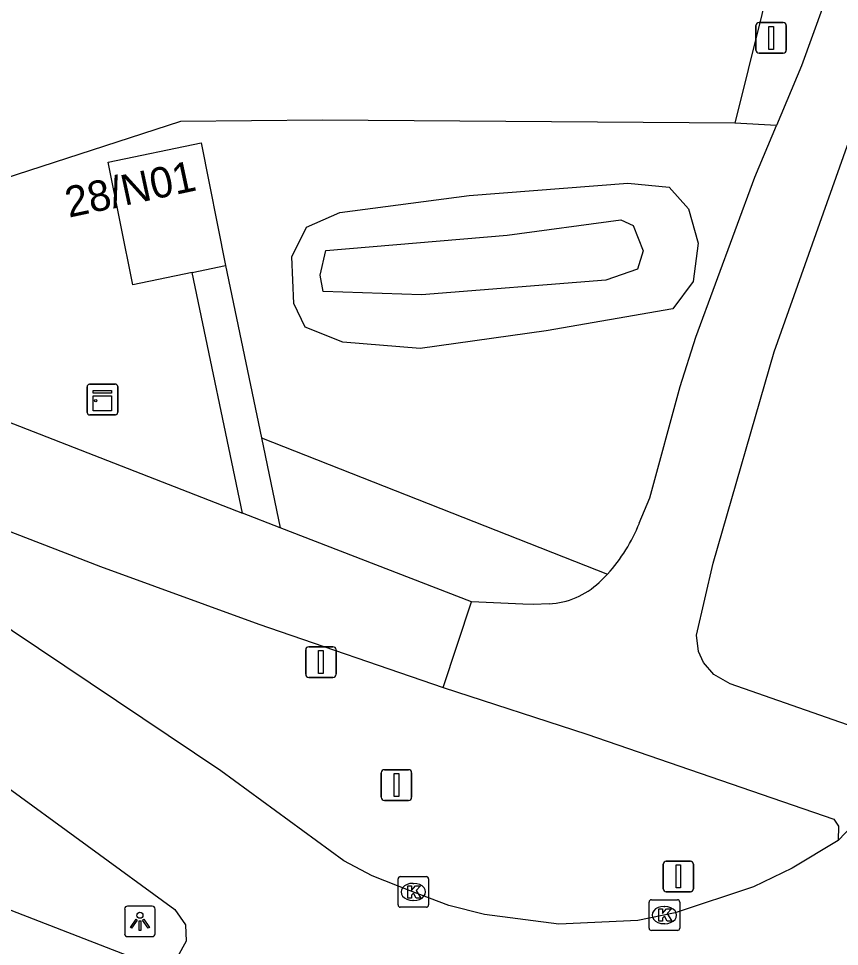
# Model space of a CAD drawing. Extents: x 156141 to 158132, y 385651 to 388399.
# Drawn here: x 156304.31 to 156331.14, y 386510.09 to 386540.41 of the extents above; entities that cross this region are included whole.
import ezdxf

# ---------------------------------------------------------------- set-up
doc = ezdxf.new("R2010")
doc.units = 0
for name, color, linetype in [('IMGEO_Berm_groen', 7, 'Continuous'), ('IMGEO_Bouwland', 7, 'Continuous'), ('IMGEO_Fietspad_gesloten', 7, 'Continuous'), ('IMGEO_Groenvoorziening', 7, 'Continuous'), ('IMGEO_Kast', 7, 'Continuous'), ('IMGEO_Kolk', 7, 'Continuous'), ('IMGEO_Lichtpunt', 7, 'Continuous'), ('IMGEO_Pand', 7, 'Continuous'), ('IMGEO_Pand_nummerreeks', 7, 'Continuous'), ('IMGEO_Rijbaan_lokaal_gesloten', 7, 'Continuous'), ('IMGEO_Verkeersbordpaal', 7, 'Continuous'), ('IMGEO_Voetpad_open', 7, 'Continuous')]:
    doc.layers.add(name, color=color, linetype=linetype)

msp = doc.modelspace()

# ---------------------------------------------------------------- linework, layer by layer
at = {"layer": 'IMGEO_Berm_groen'}
for points in [[(156358.914, 386681.214), (156356.118, 386665.332), (156348.768, 386626.891), (156344.27, 386606.243), (156337.845, 386577.757), (156327.718, 386536.986)], [(156329.08, 386536.913), (156327.718, 386536.986)], [(156312.247, 386526.707), (156323.558, 386522.259)]]:
    msp.add_lwpolyline(points, dxfattribs=at)
at = {"layer": 'IMGEO_Bouwland'}
msp.add_lwpolyline([(156327.718, 386536.986), (156314.236, 386537.081), (156309.604, 386537.043), (156302.98, 386534.895), (156300.78, 386542.538), (156301.952, 386551.718)], dxfattribs=at)
at = {"layer": 'IMGEO_Fietspad_gesloten'}
for points in [[(156348.163, 386611.714), (156343.943, 386590.004), (156341.252, 386578.081), (156338.908, 386569.228), (156337.052, 386561.839), (156334.06, 386550.854), (156331.742, 386543.951), (156329.901, 386538.856), (156329.08, 386536.913)], [(156334.214, 386516.809), (156333.87, 386516.678), (156333.544, 386516.668), (156331.617, 386517.261), (156327.569, 386518.673), (156327.033, 386518.98), (156326.698, 386519.369), (156326.529, 386519.727), (156326.464, 386520.258), (156327.01, 386522.618), (156329, 386529.519), (156331.388, 386536.237), (156333.27, 386540.153), (156340.71, 386545.321), (156341.097, 386545.374), (156341.486, 386545.29), (156341.773, 386545.133), (156341.96, 386544.868), (156341.997, 386543.534)], [(156324.596, 386523.924), (156324.936, 386524.744), (156325.935, 386528.385), (156326.447, 386529.996), (156328.367, 386535.225), (156329.08, 386536.913)], [(156299.915, 386528.814), (156311.622, 386524.249)], [(156292.75, 386528.181), (156300.726, 386524.92), (156306.982, 386522.509), (156312.164, 386520.621), (156318.18, 386518.557)], [(156312.861, 386523.766), (156311.622, 386524.249)], [(156319.111, 386521.349), (156312.861, 386523.766)], [(156323.558, 386522.259), (156323.283, 386521.987)], [(156318.18, 386518.557), (156319.111, 386521.349)], [(156321.646, 386521.284), (156321.133, 386521.268), (156320.786, 386521.275), (156319.111, 386521.349)], [(156318.18, 386518.557), (156322.883, 386517.032), (156330.955, 386514.254), (156331.103, 386514.021), (156331.099, 386513.557)]]:
    msp.add_lwpolyline(points, dxfattribs=at)
for centre, radius, start, end in [((156319.467, 386525.966), 5.521, 317.8239, 338.2954), ((156321.502, 386523.877), 2.597, 273.1821, 313.2995)]:
    msp.add_arc(centre, radius, start, end, dxfattribs=at)
at = {"layer": 'IMGEO_Groenvoorziening'}
for points in [[(156324.217, 386535.031), (156325.576, 386534.896), (156326.203, 386534.188), (156326.521, 386533.069), (156326.359, 386531.817), (156325.692, 386530.921), (156321.551, 386530.208), (156317.436, 386529.624), (156314.905, 386529.836), (156313.679, 386530.328), (156313.301, 386531.095), (156313.239, 386532.618), (156313.717, 386533.589), (156314.803, 386534.068), (156319.03, 386534.625), (156324.217, 386535.031)], [(156317.48, 386531.375), (156314.267, 386531.49), (156314.165, 386532.027), (156314.349, 386532.826), (156320.273, 386533.334), (156323.996, 386533.828), (156324.395, 386533.645), (156324.723, 386532.819), (156324.54, 386532.22), (156323.498, 386531.855), (156317.48, 386531.375)]]:
    msp.add_lwpolyline(points, dxfattribs=at)
at = {"layer": 'IMGEO_Kast'}
for p, q in [((156306.625, 386528.461), (156307.466, 386528.461)), ((156307.466, 386528.461), (156306.625, 386528.461)), ((156306.55, 386527.536), (156306.55, 386528.377)), ((156306.55, 386528.377), (156306.55, 386527.536)), ((156307.55, 386528.386), (156307.55, 386527.545)), ((156307.55, 386527.545), (156307.55, 386528.386)), ((156307.475, 386527.461), (156306.634, 386527.461)), ((156306.634, 386527.461), (156307.475, 386527.461))]:
    msp.add_line(p, q, dxfattribs=at)
for points in [[(156306.745, 386528.251), (156307.345, 386528.251), (156307.345, 386528.166), (156306.745, 386528.166), (156306.745, 386528.251)], [(156306.745, 386528.076), (156307.345, 386528.076), (156307.345, 386527.587), (156306.745, 386527.587), (156306.745, 386528.076)]]:
    msp.add_lwpolyline(points, dxfattribs=at)
msp.add_circle((156306.829, 386527.925), 0.0377, dxfattribs=at)
for centre, start, end in [((156306.628, 386528.383), 92.4484, 184.2845), ((156306.628, 386528.383), 92.4484, 184.2845), ((156307.472, 386528.383), 2.4484, 94.2845), ((156307.472, 386528.383), 2.4484, 94.2845), ((156307.472, 386527.539), 272.4484, 4.2845), ((156307.472, 386527.539), 272.4484, 4.2845), ((156306.628, 386527.539), 182.4484, 274.2845), ((156306.628, 386527.539), 182.4484, 274.2845)]:
    msp.add_arc(centre, 0.0779, start, end, dxfattribs=at)
at = {"layer": 'IMGEO_Kolk'}
for p, q in [((156316.709, 386511.449), (156316.709, 386512.301)), ((156316.784, 386512.375), (156317.636, 386512.375)), ((156317.197, 386512.155), (156317.222, 386512.155)), ((156317.71, 386512.301), (156317.71, 386511.449)), ((156317.22, 386511.595), (156317.195, 386511.595)), ((156324.914, 386510.692), (156324.914, 386511.544)), ((156324.989, 386511.618), (156325.841, 386511.618)), ((156325.915, 386511.544), (156325.915, 386510.692)), ((156317.636, 386511.375), (156316.784, 386511.375)), ((156325.402, 386511.398), (156325.427, 386511.398)), ((156325.841, 386510.618), (156324.989, 386510.618)), ((156325.425, 386510.838), (156325.4, 386510.838))]:
    msp.add_line(p, q, dxfattribs=at)
for points in [[(156316.709, 386511.449), (156316.709, 386512.301)], [(156316.784, 386512.375), (156317.636, 386512.375)], [(156317.71, 386512.301), (156317.71, 386511.449)], [(156317.03, 386512.075), (156317.153, 386512.075), (156317.153, 386511.924), (156317.283, 386512.075), (156317.447, 386512.075), (156317.301, 386511.924), (156317.454, 386511.675), (156317.302, 386511.675), (156317.217, 386511.839), (156317.153, 386511.772), (156317.153, 386511.675), (156317.03, 386511.675), (156317.03, 386512.075)], [(156324.914, 386510.692), (156324.914, 386511.544)], [(156324.989, 386511.618), (156325.841, 386511.618)], [(156325.915, 386511.544), (156325.915, 386510.692)], [(156317.636, 386511.375), (156316.784, 386511.375)], [(156325.235, 386511.318), (156325.358, 386511.318), (156325.358, 386511.167), (156325.488, 386511.318), (156325.652, 386511.318), (156325.506, 386511.167), (156325.659, 386510.918), (156325.507, 386510.918), (156325.422, 386511.082), (156325.358, 386511.015), (156325.358, 386510.918), (156325.235, 386510.918), (156325.235, 386511.318)], [(156325.841, 386510.618), (156324.989, 386510.618)]]:
    msp.add_lwpolyline(points, dxfattribs=at)
for centre, start, end in [((156316.786, 386512.299), 91.552, 178.448), ((156316.786, 386512.299), 91.552, 178.448), ((156317.634, 386512.299), 1.552, 88.448), ((156317.634, 386512.299), 1.552, 88.448), ((156324.991, 386511.542), 91.552, 178.448), ((156324.991, 386511.542), 91.552, 178.448), ((156325.839, 386511.542), 1.552, 88.448), ((156325.839, 386511.542), 1.552, 88.448), ((156316.786, 386511.451), 181.552, 268.448), ((156316.786, 386511.451), 181.552, 268.448), ((156317.634, 386511.451), 271.552, 358.448), ((156317.634, 386511.451), 271.552, 358.448), ((156324.991, 386510.694), 181.552, 268.448), ((156324.991, 386510.694), 181.552, 268.448), ((156325.839, 386510.694), 271.552, 358.448), ((156325.839, 386510.694), 271.552, 358.448)]:
    msp.add_arc(centre, 0.0765, start, end, dxfattribs=at)
for centre, major_axis, ratio, start_param, end_param in [((156317.196, 386511.875), (-0.387, 0.002), 0.722429, 4.712389, 7.853982), ((156317.221, 386511.875), (-0.39, 0.002), 0.717154, 1.570796, 4.712389), ((156325.401, 386511.118), (-0.387, 0.002), 0.722429, 4.712389, 7.853982), ((156325.426, 386511.118), (-0.39, 0.002), 0.717154, 1.570796, 4.712389)]:
    msp.add_ellipse(centre, major_axis=major_axis, ratio=ratio, start_param=start_param, end_param=end_param, dxfattribs=at)
at = {"layer": 'IMGEO_Lichtpunt'}
for p, q in [((156307.776, 386511.317), (156307.776, 386510.51)), ((156307.776, 386511.317), (156307.776, 386510.51)), ((156308.678, 386511.412), (156307.87, 386511.412)), ((156308.678, 386511.412), (156307.87, 386511.412)), ((156308.772, 386510.51), (156308.772, 386511.317)), ((156308.772, 386510.51), (156308.772, 386511.317)), ((156307.87, 386510.416), (156308.678, 386510.416)), ((156307.87, 386510.416), (156308.678, 386510.416))]:
    msp.add_line(p, q, dxfattribs=at)
for points in [[(156308.15, 386510.981), (156308.189, 386510.953), (156308.001, 386510.691), (156307.963, 386510.718), (156308.15, 386510.981)], [(156308.252, 386510.933), (156308.299, 386510.933), (156308.299, 386510.611), (156308.252, 386510.611), (156308.252, 386510.933)], [(156308.362, 386510.953), (156308.4, 386510.98), (156308.587, 386510.718), (156308.548, 386510.69), (156308.362, 386510.953)]]:
    msp.add_lwpolyline(points, dxfattribs=at)
msp.add_circle((156308.275, 386511.115), 0.0994, dxfattribs=at)
for centre, start, end in [((156307.87, 386511.317), 90, 180), ((156307.87, 386511.317), 90, 180), ((156308.678, 386511.317), 0, 90), ((156308.678, 386511.317), 0, 90), ((156307.87, 386510.51), 180, 270), ((156307.87, 386510.51), 180, 270), ((156308.678, 386510.51), 270, 0), ((156308.678, 386510.51), 270, 360)]:
    msp.add_arc(centre, 0.0946, start, end, dxfattribs=at)
at = {"layer": 'IMGEO_Pand'}
for points in [[(156309.985, 386532.114), (156308.042, 386531.705), (156307.234, 386535.712), (156310.277, 386536.35), (156311.07, 386532.343)], [(156309.985, 386532.114), (156311.07, 386532.343)]]:
    msp.add_lwpolyline(points, dxfattribs=at)
at = {"layer": 'IMGEO_Rijbaan_lokaal_gesloten'}
for points in [[(156279.45, 386524.804), (156292.191, 386519.892), (156293.29, 386519.47), (156293.425, 386519.418), (156303.669, 386515.482), (156309.414, 386511.3), (156309.768, 386510.799), (156309.786, 386510.272), (156309.503, 386509.752), (156309.018, 386509.516), (156308.448, 386509.57), (156294.031, 386515.158), (156293.895, 386515.211), (156292.782, 386515.644), (156280.043, 386520.581)], [(156331.099, 386513.557), (156329.596, 386512.65), (156328.331, 386512.037), (156325.767, 386511.191), (156324.552, 386510.938), (156321.96, 386510.826), (156319.539, 386511.139), (156318.366, 386511.435), (156317.104, 386511.915), (156315.868, 386512.406), (156314.943, 386512.888), (156310.923, 386515.834), (156304.102, 386520.406), (156302.029, 386522.003)], [(156334.214, 386516.809), (156331.099, 386513.557)]]:
    msp.add_lwpolyline(points, dxfattribs=at)
at = {"layer": 'IMGEO_Verkeersbordpaal'}
for p, q in [((156328.408, 386539.374), (156328.408, 386540.174)), ((156328.408, 386540.174), (156328.408, 386539.374)), ((156328.508, 386540.274), (156329.298, 386540.274)), ((156329.298, 386540.274), (156328.508, 386540.274)), ((156329.398, 386540.174), (156329.398, 386539.374)), ((156329.398, 386539.374), (156329.398, 386540.174)), ((156329.298, 386539.274), (156328.508, 386539.274)), ((156328.508, 386539.274), (156329.298, 386539.274)), ((156313.694, 386518.984), (156313.694, 386519.784)), ((156313.694, 386519.784), (156313.694, 386518.984)), ((156313.794, 386519.884), (156314.584, 386519.884)), ((156314.584, 386519.884), (156313.794, 386519.884)), ((156314.684, 386519.784), (156314.684, 386518.984)), ((156314.684, 386518.984), (156314.684, 386519.784)), ((156314.584, 386518.884), (156313.794, 386518.884)), ((156313.794, 386518.884), (156314.584, 386518.884)), ((156316.163, 386514.967), (156316.163, 386515.767)), ((156316.163, 386515.767), (156316.163, 386514.967)), ((156316.263, 386515.867), (156317.053, 386515.867)), ((156317.053, 386515.867), (156316.263, 386515.867)), ((156317.153, 386515.767), (156317.153, 386514.967)), ((156317.153, 386514.967), (156317.153, 386515.767)), ((156317.053, 386514.867), (156316.263, 386514.867)), ((156316.263, 386514.867), (156317.053, 386514.867)), ((156325.377, 386511.981), (156325.377, 386512.781)), ((156325.377, 386512.781), (156325.377, 386511.981)), ((156325.477, 386512.881), (156326.267, 386512.881)), ((156326.267, 386512.881), (156325.477, 386512.881)), ((156326.367, 386512.781), (156326.367, 386511.981)), ((156326.367, 386511.981), (156326.367, 386512.781)), ((156326.267, 386511.881), (156325.477, 386511.881)), ((156325.477, 386511.881), (156326.267, 386511.881))]:
    msp.add_line(p, q, dxfattribs=at)
for points in [[(156328.828, 386540.149), (156328.978, 386540.149), (156328.978, 386539.399), (156328.828, 386539.399), (156328.828, 386540.149)], [(156314.114, 386519.759), (156314.264, 386519.759), (156314.264, 386519.009), (156314.114, 386519.009), (156314.114, 386519.759)], [(156316.583, 386515.742), (156316.733, 386515.742), (156316.733, 386514.992), (156316.583, 386514.992), (156316.583, 386515.742)], [(156325.797, 386512.756), (156325.947, 386512.756), (156325.947, 386512.006), (156325.797, 386512.006), (156325.797, 386512.756)]]:
    msp.add_lwpolyline(points, dxfattribs=at)
for centre, start, end in [((156328.508, 386540.174), 90, 180), ((156328.508, 386540.174), 90, 180), ((156329.298, 386540.174), 0, 90), ((156329.298, 386540.174), 360, 90), ((156328.508, 386539.374), 180, 270), ((156328.508, 386539.374), 180, 270), ((156329.298, 386539.374), 270, 0), ((156329.298, 386539.374), 270, 0), ((156313.794, 386519.784), 90, 180), ((156313.794, 386519.784), 90, 180), ((156314.584, 386519.784), 0, 90), ((156314.584, 386519.784), 360, 90), ((156313.794, 386518.984), 180, 270), ((156313.794, 386518.984), 180, 270), ((156314.584, 386518.984), 270, 0), ((156314.584, 386518.984), 270, 0), ((156316.263, 386515.767), 90, 180), ((156316.263, 386515.767), 90, 180), ((156317.053, 386515.767), 0, 90), ((156317.053, 386515.767), 360, 90), ((156316.263, 386514.967), 180, 270), ((156316.263, 386514.967), 180, 270), ((156317.053, 386514.967), 270, 0), ((156317.053, 386514.967), 270, 0), ((156325.477, 386512.781), 90, 180), ((156325.477, 386512.781), 90, 180), ((156326.267, 386512.781), 0, 90), ((156326.267, 386512.781), 360, 90), ((156325.477, 386511.981), 180, 270), ((156325.477, 386511.981), 180, 270), ((156326.267, 386511.981), 270, 0), ((156326.267, 386511.981), 270, 0)]:
    msp.add_arc(centre, 0.1, start, end, dxfattribs=at)
at = {"layer": 'IMGEO_Voetpad_open'}
for points in [[(156311.622, 386524.249), (156309.985, 386532.114)], [(156311.07, 386532.343), (156312.247, 386526.707)], [(156312.247, 386526.707), (156312.861, 386523.766)]]:
    msp.add_lwpolyline(points, dxfattribs=at)

# ---------------------------------------------------------------- texts
at = {"layer": 'IMGEO_Pand_nummerreeks'}
msp.add_text('28/N01', height=1, rotation=12.0948, dxfattribs=at).set_placement((156305.951, 386533.898))

doc.saveas('drawing.dxf')
